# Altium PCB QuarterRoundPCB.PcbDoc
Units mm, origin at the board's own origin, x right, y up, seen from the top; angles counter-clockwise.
Board outline 60 x 60 mm, 2 copper layers (Top Layer, Bottom Layer); 24 components, 17 nets, 71 pads, 13 vias.
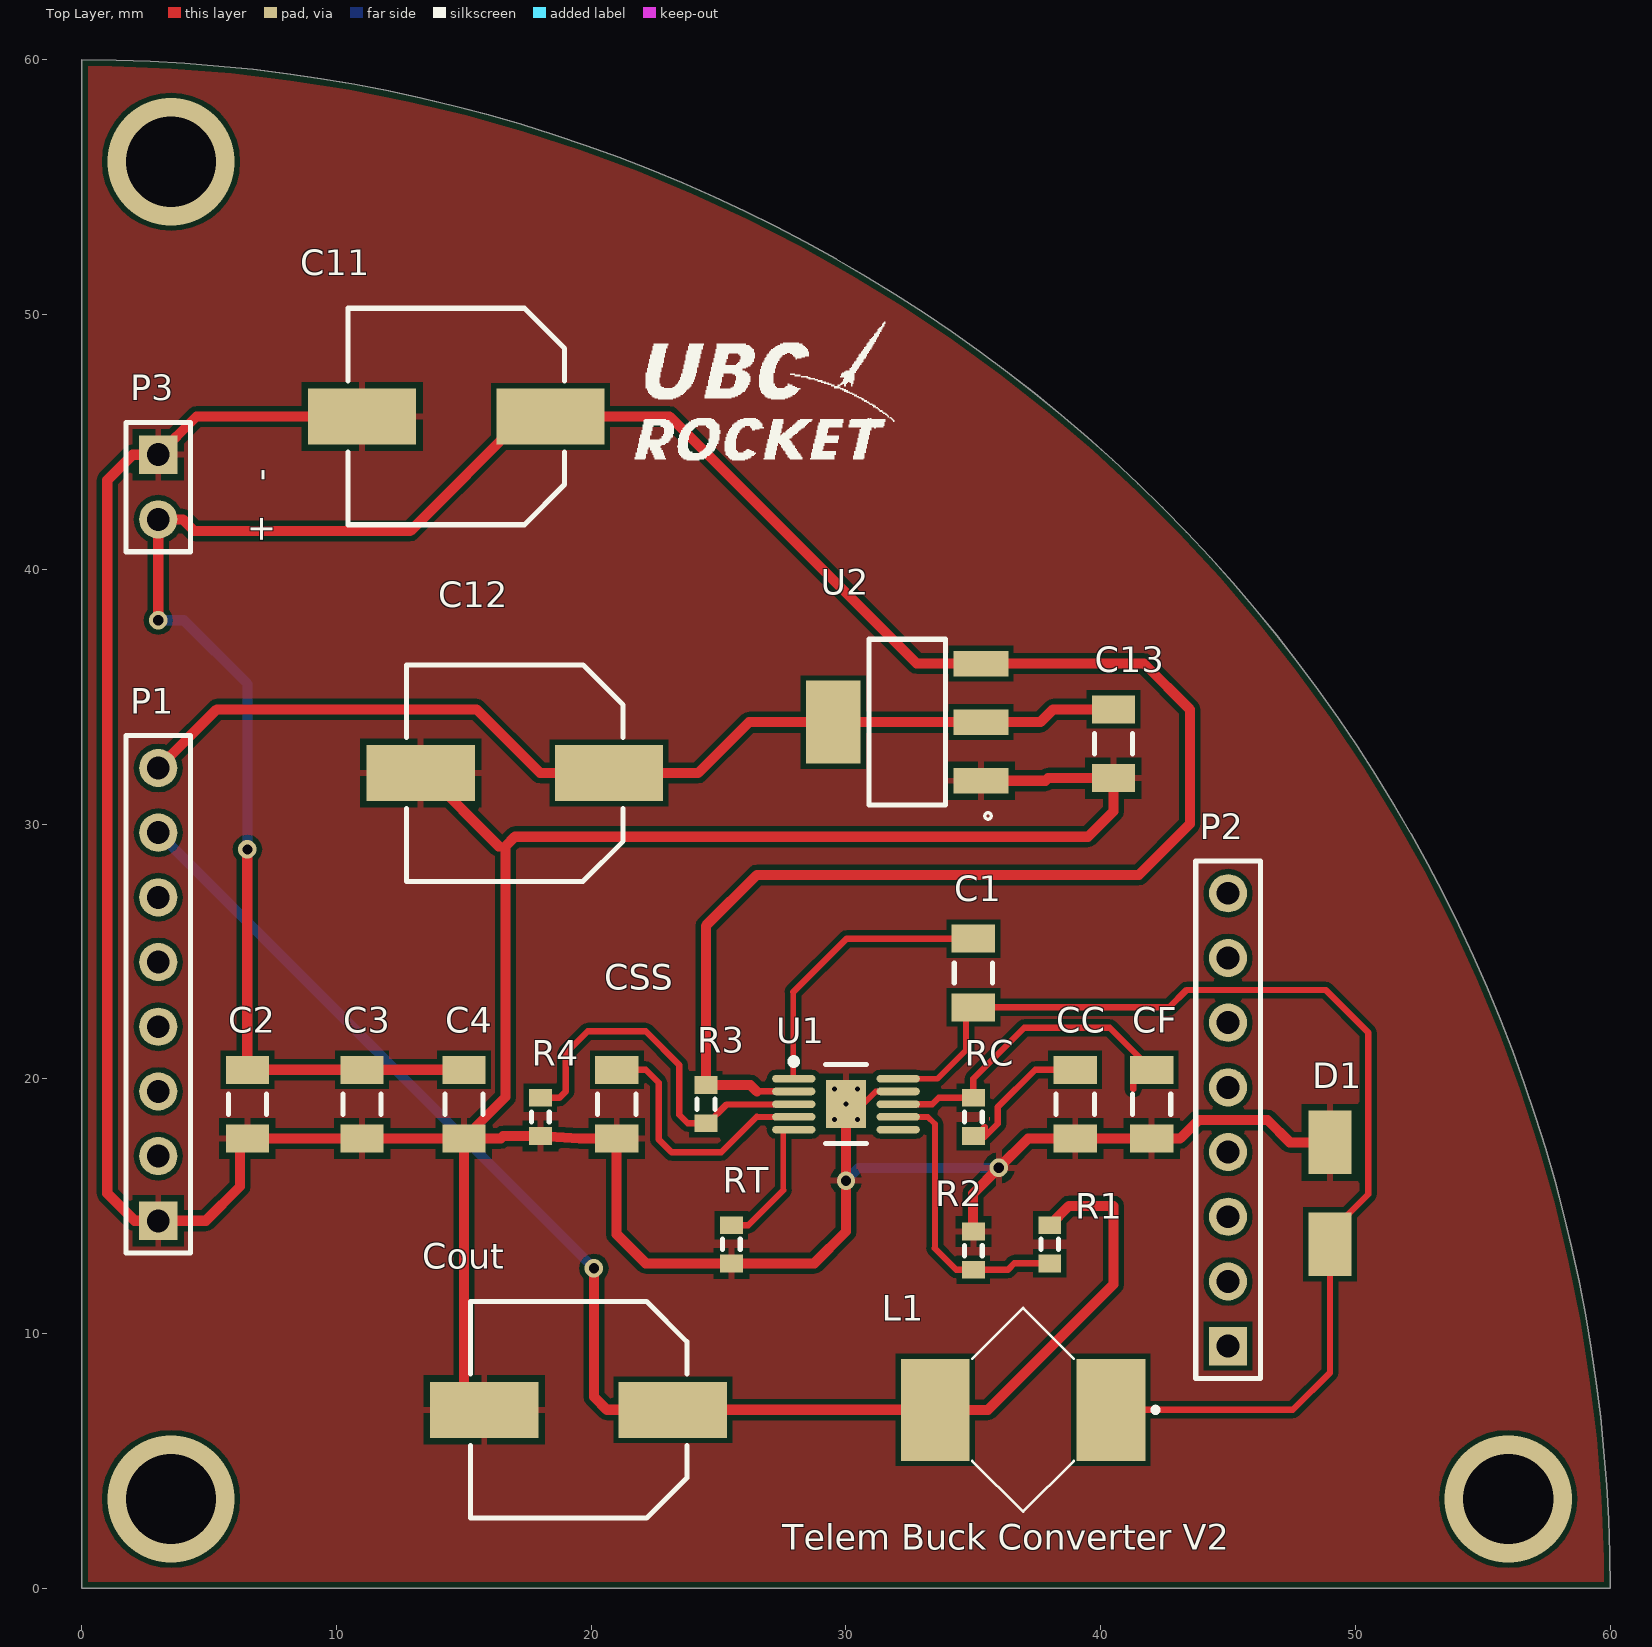
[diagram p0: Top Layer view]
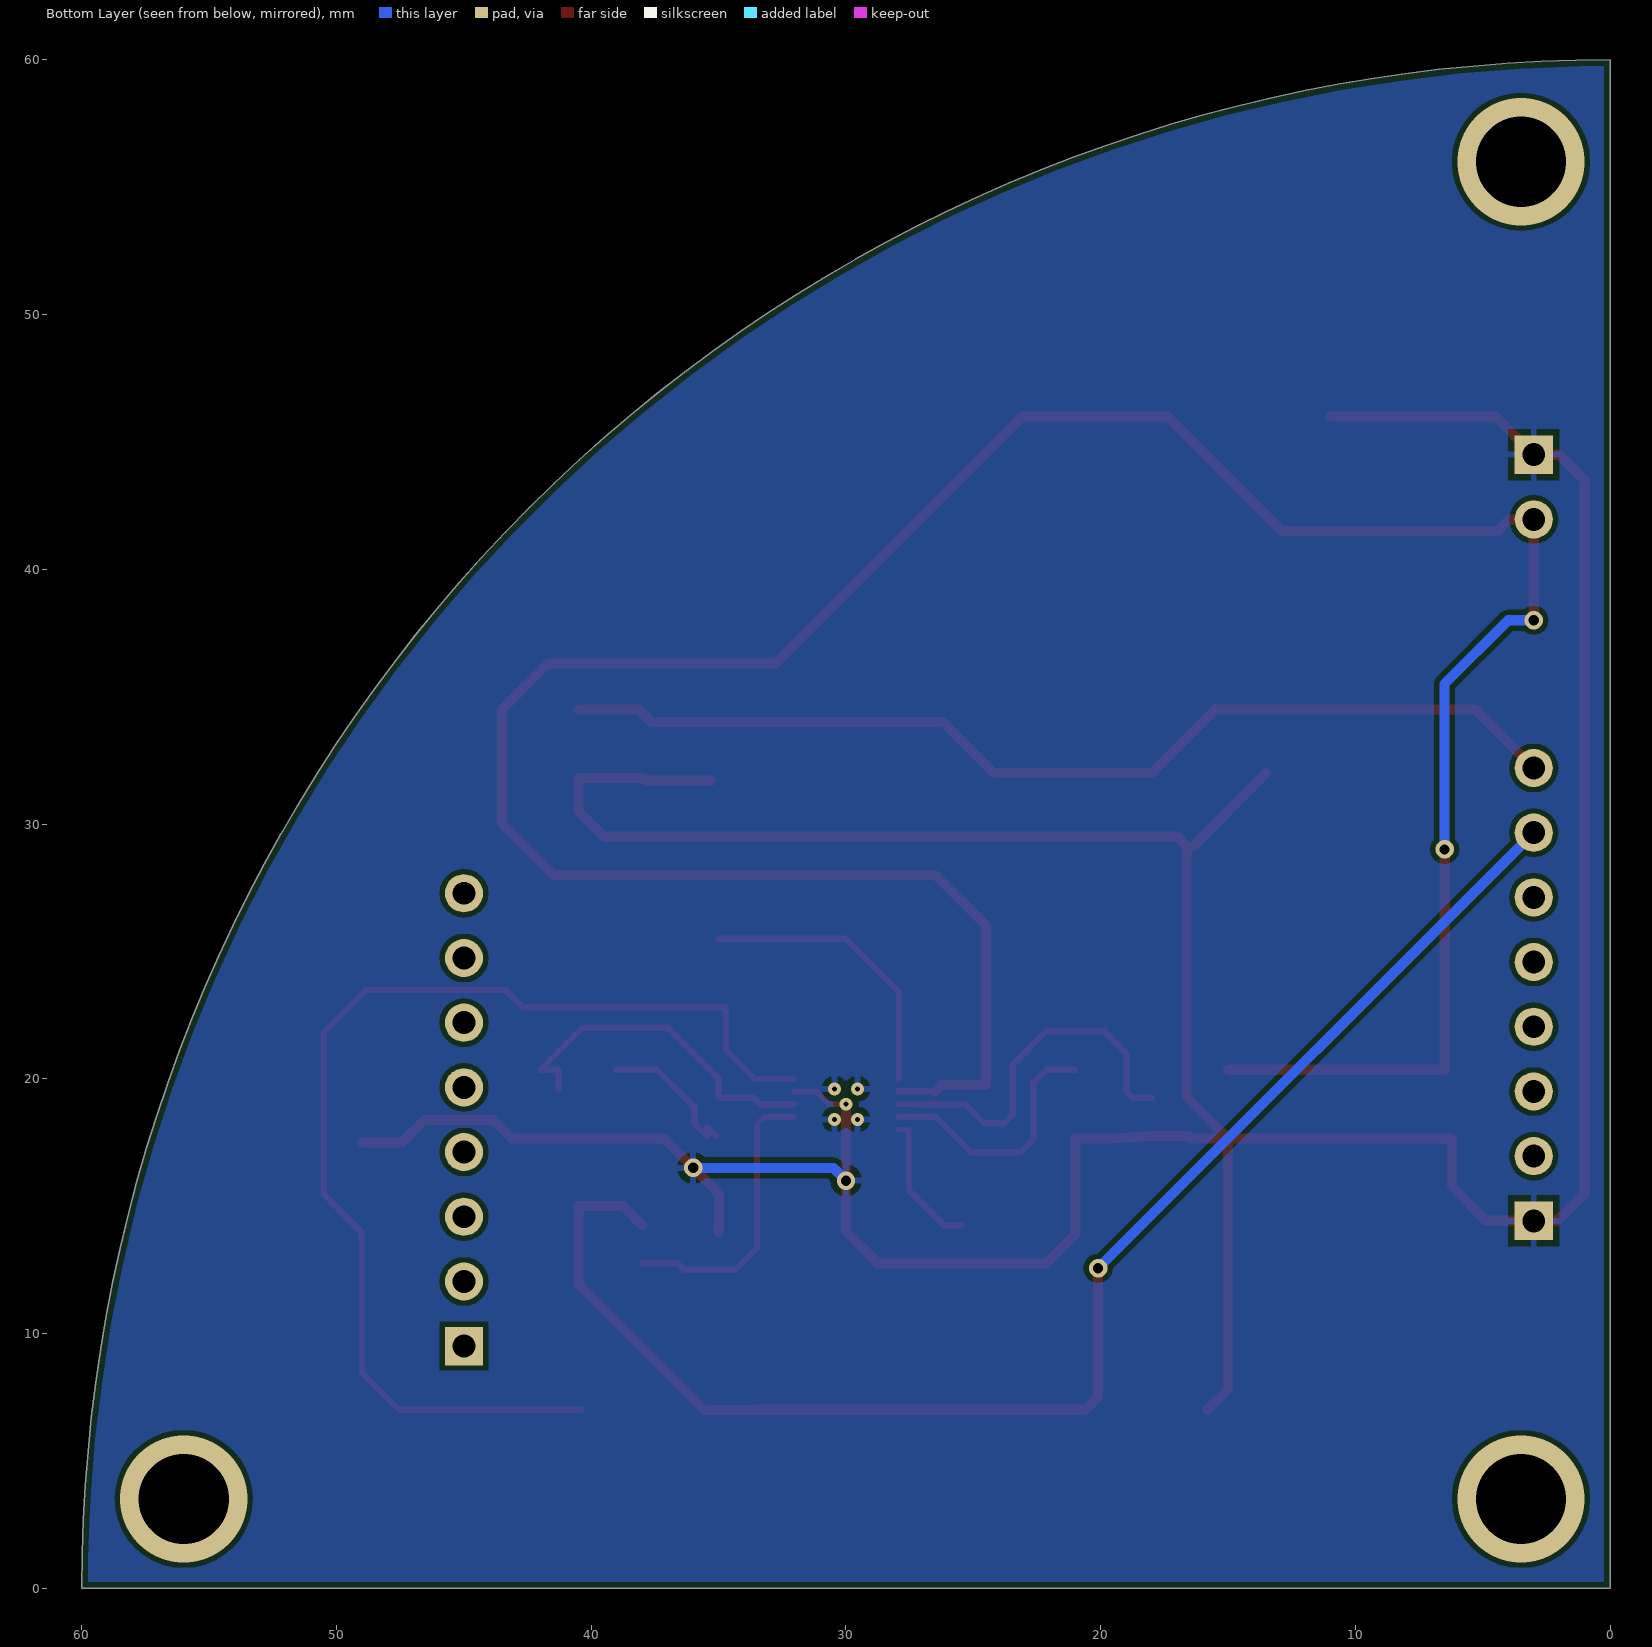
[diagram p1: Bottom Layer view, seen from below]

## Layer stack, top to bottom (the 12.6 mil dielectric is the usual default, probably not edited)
Top Solder: solder mask 0.0102, Solder Resist, Dk 3.5
Top Layer: signal copper 0.0356
Dielectric 1: dielectric 0.32, FR-4, Dk 4.8
Bottom Layer: signal copper 0.0356
Bottom Solder: solder mask 0.0102, Solder Resist, Dk 3.5

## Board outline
0,60 cw(c0,0) 60,0 0,0

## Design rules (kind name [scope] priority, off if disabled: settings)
BoardOutlineClearance [All] p1: gap=0.254 ignorepadtopadclearanceinfootprint=FALSE except(0: Arc-SplitContinuation Track-SplitContinuation SMDPad-SplitContinuation THPad-SplitContinuation Via-SplitContinuation Fill-SplitContinuation Poly-SplitContinuation Region-SplitContinuation Text-SplitContinuation)
Clearance [All] p1: gap=0.2 ignorepadtopadclearanceinfootprint=FALSE
Clearance Clearance_PWR [(InNet('ACT 12V') OR InNet('GND'))] p2: gap=0.25 ignorepadtopadclearanceinfootprint=FALSE except(0: Arc-Hole Track-Hole SMDPad-Hole THPad-Hole Via-Hole Fill-Hole Poly-Hole Region-Hole Text-Hole)
ComponentClearance [All] p1: gap=0.25 collisioncheckmode=3 verticalgap=0.25 showdistances=FALSE
Height [All] p1: minheight=0 maxheight=30 prefheight=12.7
HoleSize HoleSize_1 [IsVia] p1: absolutevalues=TRUE maxlimit=0.254 minlimit=0.025 maxpercent=80.000 minpercent=20.000
HoleSize [All] p2: absolutevalues=TRUE maxlimit=5 minlimit=0.025 maxpercent=80.000 minpercent=20.000
PlaneClearance [All] p1: clearance=1
PlaneConnect [All] p1: planeconnectstyle=Relief reliefexpansion=0.5 reliefentries=4 reliefconductorwidth=0.25 reliefairgap=0.25
PolygonConnect [All] p1: connectstyle=Relief reliefconductorwidth=0.25 reliefentries=4 polygonreliefangle="90 Angle" airgapwidth=0.25
RoutingCorners [All] p1: cornerstyle=45-Degree minsetback=0.25 maxsetback=0.25
RoutingVias [All] p1: holewidth=0.5 width=1 viastyle="Through Hole" minholewidth=0.5 minwidth=1 maxholewidth=0.5 maxwidth=1
SMDNeckDown [All] p1: percent=75.000
SilkToSilkClearance [All] p1: silktosilkclearance=0
SolderMaskExpansion [All] p1: expansion=0.1
Width "Schematic Width Constraint_6" [InNet('5V')] p1: maxlimit=0.4 minlimit=0.4 preferedwidth=0.4 minimp=50.000000 maximp=50.000000 favimp=50.000000
Width "Schematic Width Constraint_5" [InNet('GND')] p2: maxlimit=0.4 minlimit=0.4 preferedwidth=0.4 minimp=50.000000 maximp=50.000000 favimp=50.000000
Width "Schematic Width Constraint_1" [InNet('BATT')] p3: maxlimit=0.4 minlimit=0.4 preferedwidth=0.4 minimp=50.000000 maximp=50.000000 favimp=50.000000
Width "Schematic Width Constraint_2" [InNet('BATT')] p4: maxlimit=0.3 minlimit=0.3 preferedwidth=0.3 minimp=50.000000 maximp=50.000000 favimp=50.000000
Width "Schematic Width Constraint" [InNet('3.3V')] p5: maxlimit=0.4 minlimit=0.4 preferedwidth=0.4 minimp=50.000000 maximp=50.000000 favimp=50.000000
Width Width_PWR [(InNet('ACT 12V') OR InNet('GND'))] p6: maxlimit=0.4 minlimit=0.25 preferedwidth=0.3 minimp=50.000000 maximp=50.000000 favimp=50.000000
Width [All] p7: maxlimit=0.25 minlimit=0.25 preferedwidth=0.25
23 further rules are at their usual default settings.

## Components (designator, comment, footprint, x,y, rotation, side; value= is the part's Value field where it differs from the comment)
C1 "Cap Semi" C1206 35,24.15 r270 top value=0.1uF
C2 "Cap Semi" C1206 6.5,19 r90 top value=2.2uF
C3 "Cap Semi" C1206 11,19 r90 top value=2.2uF
C4 "Cap Semi" C1206 15,19 r90 top value=0.1uF
C11 "47uF 6.3V" "Panasonic Capacitor, ZA-Series, F-Size" 14.7,46 r180 top
C12 "47uF 6.3V" "Panasonic Capacitor, ZA-Series, F-Size" 17,32 r180 top
C13 "Cap Semi" C1206 40.5,33.15 r90 top value=0.1uF
CC "Cap Semi" C1206 39,19 r90 top value=2700pF
CF "Cap Semi" C1206 42,19 r90 top value=6.8pF
Cout "47uF 6.3V" "Panasonic Capacitor, ZA-Series, F-Size" 19.5,7 r180 top
CSS "Cap Semi" C1206 21,19 r90 top value=0.01uF
D1 "" SMA-DIODE 48.985,15.508 r270 top
L1 "10uH" CDR7D28MNNP101NC 37.2,7 r180 top
P1 "Header 8" HDR1X8 3,14.42 r90 top
P2 "Header 8" HDR1X8 45,9.5 r90 top
P3 "Header 2" HDR1X2 3,44.5 r270 top
R1 "Res3" J1-0603 38,13.5 r90 top value=31.6K
R2 "Res3" J1-0603 35,13.25 r270 top value=10K
R3 "Res3" J1-0603 24.5,19 r90 top value=332K
R4 "Res3" J1-0603 18,18.5 r90 top value=61.9K
RC "Res3" J1-0603 35,18.5 r90 top value=90.9K
RT "Res3" J1-0603 25.5,13.5 r90 top value=90.9K
U1 "TPS54140DGQ" DGQ10-1675X1445TP_N 30,19 r0 top
U2 "NCP1117ST50T3G" SOT230P700X180-4N 32.4,34 r180 top

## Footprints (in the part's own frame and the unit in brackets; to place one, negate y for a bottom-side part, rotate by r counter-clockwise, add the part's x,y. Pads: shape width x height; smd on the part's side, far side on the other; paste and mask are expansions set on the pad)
C1206 [mm] "Chip Capacitor, Body 3.2x1.6mm, IPC High Density"
  rect 1.1x1.7 smd: 1(-1.35,0) 2(1.35,0)
  silkscreen extent -0.4,-0.75 0.4,0.75, body extent -1.7,-0.9 1.7,0.9, height 1.3
CDR7D28MNNP101NC [mm]
  rect 2.7x4 smd: 1(-3.2,0) 2(3.7,0)
  silkscreen extent -5.05,-4 2.25,4
DGQ10-1675X1445TP_N [mm] "TSSOP, 10-Leads, Body 3x3mm, Pitch 0.5mm, Thermal Pad 1.88x1.57mm, IPC Medium Density"
  oval 1.7x0.3 smd: 1(-2.05,1) 2(-2.05,0.5) 3(-2.05,0) 4(-2.05,-0.5) 5(-2.05,-1) 6(2.05,-1) 7(2.05,-0.5) 8(2.05,0) 9(2.05,0.5) 10(2.05,1)
  rect 1.57x1.88 smd: 11(0,0)
  silkscreen extent -2.17,-1.55 0.8,1.8, body extent -1.55,-1.55 1.55,1.55, height 1.1
HDR1X2 [mm] "Connector; Header; 2 Position"
  rect 1.5x1.5 hole 0.9: 1(0,0)
  round 1.5 hole 0.9: 2(2.54,0)
  silkscreen extent -1.27,-1.27 3.81,1.27
HDR1X8 [mm] "Connector; Header; 8 Position"
  rect 1.5x1.5 hole 0.9: 1(0,0)
  round 1.5 hole 0.9: 2(2.54,0) 3(5.08,0) 4(7.62,0) 5(10.16,0) 6(12.7,0) 7(15.24,0) 8(17.78,0)
  silkscreen extent -1.27,-1.27 19.05,1.27
J1-0603 [mm] "Chip Resistor, Body 1.6x0.8mm, IPC High Density"
  rect 0.7x0.9 smd: 1(-0.75,0) 2(0.75,0)
  silkscreen extent -0.2,-0.35 0.2,0.35, body extent -0.85,-0.48 0.85,0.48, height 0.9
"Panasonic Capacitor, ZA-Series, F-Size" [mm]
  rect 4.25x2.2 smd: 1(-3.7,0) 2(3.7,0)
  silkscreen extent -4.25,-4.25 4.25,4.25, body extent -5.02,-4.25 5.02,4.25, height 10.5
SMA-DIODE [mm]
  rect 2.5x1.7 smd: 1(-1.992,0.015) 2(2.008,0.015)
SOT230P700X180-4N [mm]
  rect 2.15x1 smd: 1(-2.9,2.3) 2(-2.9,0) 3(-2.9,-2.3)
  rect 2.15x3.25 smd: 4(2.9,0)
  silkscreen extent -3.3,-3.25 1.5,3.81

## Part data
C1 C2 C3 C4 C13 CC CF CSS: "Capacitor (Semiconductor SIM Model)"
C11 C12 Cout: library part "Panasonic 150uF 35V", "EEHZA1V151V 150uF 35V Hyprid Cap Vibration-Proof", Supplier Part Number 1=P19824CT-ND
D1: library part B220A-13-F, "B220A Series 20 V 2 A Surface Mount Schottky Barrier Rectifier - SMA", Package="DO-214 Diodes Inc."
L1: library part CDR7D28MNNP-101NC, "Fixed Inductors 100uH .65A", Manufacturer_Name=Sumida
P1 P2: "Header, 8-Pin"
P3: "Header, 2-Pin"
R1 R2 R3 R4 RC RT: "Resistor"
U1: "Buck Inverting Buck-Boost Step Down Regulator with 3.5 to 42 V Input and 0.8 to 39 V Output, -40 to 150 degC, 10-Pin MSOP-PowerPAD (DGQ), Green (RoHS & no Sb/Br)", Manufacturer="Texas Instruments", Rating=Catalog, Supplier Part Number 1=296-23970-5-ND, Switch Current Limit(Typ)(A)=1.8
U2: Package="TO-261-4 HTC Korea"

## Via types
v1: diameter 0.725, hole 0.406, Top Layer to Bottom Layer, 5 vias
v2: diameter 0.5, hole 0.2, Top Layer to Bottom Layer, 5 vias
v3: diameter 5, hole 3.54, Top Layer to Bottom Layer, 3 vias

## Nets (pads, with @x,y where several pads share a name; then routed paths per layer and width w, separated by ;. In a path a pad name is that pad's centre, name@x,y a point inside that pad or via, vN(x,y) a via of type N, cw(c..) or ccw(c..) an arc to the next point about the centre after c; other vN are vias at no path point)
3.3V: Cout.1 L1.2 P1.7 R1.2 | length 57.8
  Top Layer w0.4: v1(20.104,12.556) 20.104,7.508 20.612,7 Cout.1 L1.2 33.5,6.998 35.573,6.998 40.5,11.925 40.5,15 38.75,15 R1.2
  Bottom Layer w0.4: P1.7 v1(20.104,12.556)
5V: C12.1 C13.2 P1.8 U2.2 U2.4 | length 40.5
  Top Layer w0.4: P1.8 5.3,34.5 15.496,34.5 17.996,32 20.9,32 24.193,32 26.193,34 U2.4 U2.2 37.63,34 38.13,34.5 C13.2
"ACT 24V": P1.4
BATT: C2.2 C3.2 C4.2 C11.1 P3.2 R3.2 U1.2 U2.3 | length 114.2
  Top Layer w0.254: 26.5,19.5 U1.2
  Top Layer w0.4: v1@3,38.212 P3.2 3.965,41.96 4.425,41.5 12.886,41.5 17.386,46 C11.1 23.076,46 32.776,36.3 U2.3 41.7,36.3 43.5,34.5 43.5,30 41.5,28 26.501,28 24.5,25.999 R3.2 26.25,19.75 26.5,19.5 ; v1@6.49,29 6.49,20.35 C2.2 C3.2 C4.2
  Bottom Layer w0.4: v1(3,38) 4,38 6.5,35.5 v1(6.5,29)
CAN_5V: P1.2
GND: C2.1 C3.1 C4.1 C11.2 C12.2 C13.1 CC.1 CF.1 Cout.2 CSS.1 D1.1 P1.1 P3.1 R2.1 R4.1 RT.1 U1.9 U1.11 U2.1 | length 164.4
  Top Layer w0.225: v2(30,19) 30.67,19 31.17,19.5 U1.9
  Top Layer w0.4: C11.2 4.5,46 P3.1 2,44.5 1,43.5 1,15.5 2.08,14.42 P1.1 4.864,14.42 6.21,15.766 6.21,17.65 C2.1 C3.1 C4.1 ; C12.2@13.5,32 16.37,29.13 ; Cout.2 15,7.8 C4.1 ; CSS.1 CSS.1@20.993,17.65 ; v2(30,19) 30,14 28.75,12.75 RT.1 22.136,12.75 20.993,13.893 CSS.1@20.993,17.65 ; R2.1 34.988,14 34.988,15.488 v1(36,16.5) 37.15,17.65 CC.1 CF.1 43.116,17.65 43.843,18.377 46.545,18.377 47.422,17.5 D1.1 ; U2.1 37.833,31.7 37.933,31.8 C13.1 40.5,30.5 39.5,29.5 17,29.5 16.63,29.13 16.63,19.28 C4.1 ; C4.1 16.446,17.65 16.546,17.75 R4.1 19.544,17.65 CSS.1@20.993,17.65
  Bottom Layer w0.4: v1(30,16) 30.5,16.5 v1(36,16.5)
  other v2: 29.55,18.4 30.45,18.4 29.55,19.6 30.45,19.6
NetC1_1: C1.1 U1.1 | length 11.4
  Top Layer w0.225: 27.927,23.406 27.927,20 U1.1
  Top Layer w0.25: 27.927,23.406 30.021,25.5 C1.1
NetC1_2: C1.2 D1.2 L1.1 U1.10 | length 44.7
  Top Layer w0.225: U1.10 33.589,20 34.709,21.12
  Top Layer w0.25: 34.709,21.12 34.709,22.8 C1.2 42.688,22.8 43.37,23.482 48.831,23.482 50.5,21.814 50.5,15.457 49,13.957 D1.2 49,8.462 47.536,6.998 40.4,6.998 L1.1
NetCC_2: CC.2 RC.1 | length 5.9
  Top Layer w0.25: RC.1@35.09,17.75 35.445,18.105 35.445,17.721 35.962,18.238 35.962,18.889 37.423,20.35 CC.2
NetCF_2: CF.2 RC.2 U1.8 | length 13.8
  Top Layer w0.25: U1.8 33.388,19 33.638,19.25 RC.2 35,20 37,22 40.35,22 CF.2 41.275,20.35 41.275,19.593
NetCSS_2: CSS.2 U1.4 | length 10.2
  Top Layer w0.225: 26.5,18.5 U1.4
  Top Layer w0.25: CSS.2 22.136,20.35 22.644,19.842 22.644,17.615 23.152,17.107 25.107,17.107 26.5,18.5
NetR1_1: R1.1 R2.2 U1.7 | length 11.4
  Top Layer w0.225: U1.7 33.21,18.5 33.49,18.221 33.49,13.338
  Top Layer w0.25: 33.49,13.338 34.328,12.5 R2.2 36.36,12.5 36.61,12.75 R1.1
NetR3_1: R3.1 R4.2 U1.3 | length 14.9
  Top Layer w0.225: 25.311,18.986 27.241,18.986 27.241,19 U1.3
  Top Layer w0.25: R4.2 18.75,19.25 19,19.5 19,21 19.857,21.857 22.136,21.857 23.457,20.536 23.457,18.58 23.787,18.25 R3.1 24.574,18.25 25.311,18.986
NetRT_2: RT.2 U1.5 | length 5.4
  Top Layer w0.225: 27.533,15.62 27.533,18 U1.5
  Top Layer w0.25: RT.2 26.163,14.25 27.533,15.62
SCL: P1.6
SDA: P1.5
VCC: P1.3
pads on no net: P2.1 P2.2 P2.3 P2.4 P2.5 P2.6 P2.7 P2.8 U1.6
copper on no net: | length 0.1
  Top Layer w0: 35.637,18.372 35.637,18.478
  other v3: 3.5,3.5 56,3.5 3.5,56

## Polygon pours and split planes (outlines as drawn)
GND on Bottom Layer "bottom" (solid, pour order 4): 0,60 cw(c0,0) 60,0 0,0
GND on Top Layer "Top Layer-No Net" (solid, pour order 5): 0,60 cw(c0,0) 60,0 0,0

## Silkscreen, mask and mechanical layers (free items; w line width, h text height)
Top Overlay:
  drawing of 13 lines, arcs and shapes, not listed
  text "+   -" at 7.5,41 h1 r90
  text "Telem Buck Converter V2" at 27.5,1.5 h1
Mechanical 1:
  lines w0.254: 0,60 0,0 60,0 ; 0,60.185 cw(c0,0) 60.185,0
